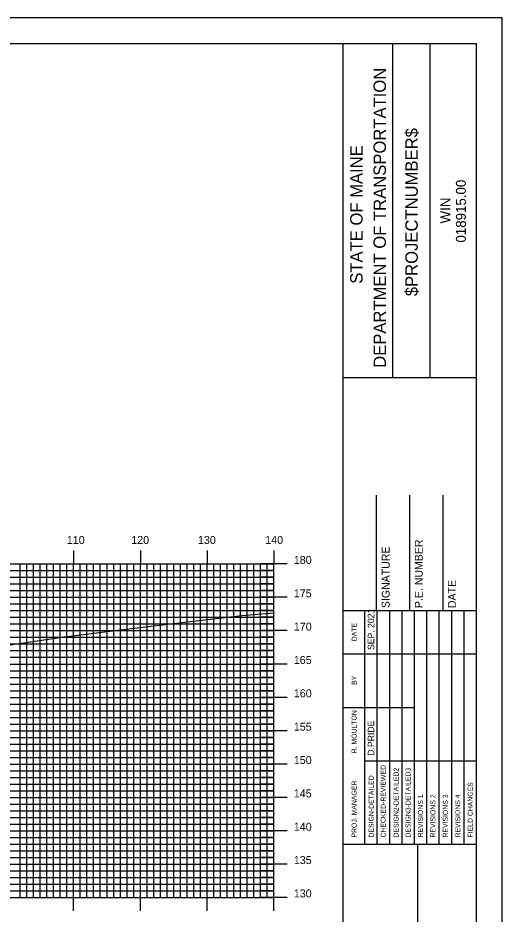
# Model space of a CAD drawing. Extents: x 1793272 to 1793615, y 442591 to 442811.
# Drawn here: x 1793539.4 to 1793612, y 442676.2 to 442810.5 of the extents above; entities that cross this region are included whole.
import ezdxf

# ---------------------------------------------------------------- set-up
doc = ezdxf.new("R2010")
doc.units = 0
for name, color, linetype in [('BORDER', 7, 'Continuous'), ('H_V ANNOTATION', 7, 'Continuous'), ('MAJOR', 7, 'Continuous'), ('MINOR', 7, 'Continuous'), ('PLOT BOUNDARY', 7, 'Continuous'), ('S_Roadway_Centerline', 7, 'Continuous')]:
    doc.layers.add(name, color=color, linetype=linetype)

msp = doc.modelspace()

# ---------------------------------------------------------------- linework, layer by layer
at = {"layer": 'BORDER'}
for p, q in [((1793588.2, 442596.67), (1793588.2, 442806.67)), ((1793595.66, 442756.66), (1793595.66, 442806.66)), ((1793601.25, 442756.66), (1793601.25, 442806.66)), ((1793588.2, 442756.65), (1793608.2, 442756.65)), ((1793593.2, 442721.67), (1793593.2, 442738.97)), ((1793598.2, 442721.67), (1793598.2, 442738.97)), ((1793603.2, 442721.67), (1793603.2, 442738.97)), ((1793588.2, 442721.67), (1793608.2, 442721.67)), ((1793588.2, 442686.67), (1793608.2, 442686.67)), ((1793599.38, 442616.67), (1793599.38, 442686.67))]:
    msp.add_line(p, q, dxfattribs=at)
msp.add_lwpolyline([(1793288.2, 442596.67), (1793608.2, 442596.67), (1793608.2, 442806.67), (1793288.2, 442806.67)], close=True, dxfattribs=at)
for points in [[(1793591.43, 442715.17), (1793591.43, 442721.67)], [(1793593.3, 442686.68), (1793593.3, 442721.67)], [(1793595.16, 442721.67), (1793595.16, 442686.68)], [(1793597.02, 442686.68), (1793597.02, 442721.67)], [(1793598.89, 442686.68), (1793598.89, 442721.67)], [(1793600.75, 442686.68), (1793600.75, 442721.67)], [(1793602.61, 442686.68), (1793602.61, 442721.67)], [(1793604.48, 442686.68), (1793604.48, 442721.67)], [(1793606.34, 442686.68), (1793606.34, 442721.67)], [(1793591.43, 442686.68), (1793591.43, 442720.26)], [(1793588.2, 442715.17), (1793608.2, 442715.17)], [(1793588.2, 442707.17), (1793591.43, 442707.17)], [(1793591.43, 442707.17), (1793598.88, 442707.17)], [(1793591.43, 442699.17), (1793608.2, 442699.17)]]:
    msp.add_lwpolyline(points, dxfattribs=at)
at = {"layer": 'MAJOR'}
for p, q in [((1793547.8, 442730.67), (1793547.8, 442728.67)), ((1793557.8, 442730.67), (1793557.8, 442728.67)), ((1793567.8, 442730.67), (1793567.8, 442728.67)), ((1793577.8, 442730.67), (1793577.8, 442728.67)), ((1793297.8, 442728.67), (1793577.8, 442728.67)), ((1793297.8, 442728.67), (1793577.8, 442728.67)), ((1793547.8, 442678.67), (1793547.8, 442728.67)), ((1793557.8, 442678.67), (1793557.8, 442728.67)), ((1793567.8, 442678.67), (1793567.8, 442728.67)), ((1793579.8, 442728.67), (1793575.8, 442728.67)), ((1793577.8, 442678.67), (1793577.8, 442728.67)), ((1793577.8, 442678.67), (1793577.8, 442728.67)), ((1793297.8, 442723.67), (1793577.8, 442723.67)), ((1793579.8, 442723.67), (1793575.8, 442723.67)), ((1793297.8, 442718.67), (1793577.8, 442718.67)), ((1793579.8, 442718.67), (1793575.8, 442718.67)), ((1793297.8, 442713.67), (1793577.8, 442713.67)), ((1793579.8, 442713.67), (1793575.8, 442713.67)), ((1793297.8, 442708.67), (1793577.8, 442708.67)), ((1793579.8, 442708.67), (1793575.8, 442708.67)), ((1793297.8, 442703.67), (1793577.8, 442703.67)), ((1793579.8, 442703.67), (1793575.8, 442703.67)), ((1793297.8, 442698.67), (1793577.8, 442698.67)), ((1793579.8, 442698.67), (1793575.8, 442698.67)), ((1793297.8, 442693.67), (1793577.8, 442693.67)), ((1793579.8, 442693.67), (1793575.8, 442693.67)), ((1793297.8, 442688.67), (1793577.8, 442688.67)), ((1793579.8, 442688.67), (1793575.8, 442688.67)), ((1793297.8, 442683.67), (1793577.8, 442683.67)), ((1793579.8, 442683.67), (1793575.8, 442683.67)), ((1793297.8, 442678.67), (1793577.8, 442678.67)), ((1793297.8, 442678.67), (1793577.8, 442678.67)), ((1793547.8, 442676.66), (1793547.8, 442678.67)), ((1793557.8, 442676.66), (1793557.8, 442678.67)), ((1793567.8, 442676.66), (1793567.8, 442678.67)), ((1793579.8, 442678.67), (1793575.8, 442678.67)), ((1793577.8, 442676.66), (1793577.8, 442678.67))]:
    msp.add_line(p, q, dxfattribs=at)
at = {"layer": 'MINOR'}
for p, q in [((1793539.8, 442678.67), (1793539.8, 442728.67)), ((1793540.8, 442678.67), (1793540.8, 442728.67)), ((1793541.8, 442678.67), (1793541.8, 442728.67)), ((1793542.8, 442678.67), (1793542.8, 442728.67)), ((1793543.8, 442678.67), (1793543.8, 442728.67)), ((1793544.8, 442678.67), (1793544.8, 442728.67)), ((1793545.8, 442678.67), (1793545.8, 442728.67)), ((1793546.8, 442678.67), (1793546.8, 442728.67)), ((1793548.8, 442678.67), (1793548.8, 442728.67)), ((1793549.8, 442678.67), (1793549.8, 442728.67)), ((1793550.8, 442678.67), (1793550.8, 442728.67)), ((1793551.8, 442678.67), (1793551.8, 442728.67)), ((1793552.8, 442678.67), (1793552.8, 442728.67)), ((1793553.8, 442678.67), (1793553.8, 442728.67)), ((1793554.8, 442678.67), (1793554.8, 442728.67)), ((1793555.8, 442678.67), (1793555.8, 442728.67)), ((1793556.8, 442678.67), (1793556.8, 442728.67)), ((1793558.8, 442678.67), (1793558.8, 442728.67)), ((1793559.8, 442678.67), (1793559.8, 442728.67)), ((1793560.8, 442678.67), (1793560.8, 442728.67)), ((1793561.8, 442678.67), (1793561.8, 442728.67)), ((1793562.8, 442678.67), (1793562.8, 442728.67)), ((1793563.8, 442678.67), (1793563.8, 442728.67)), ((1793564.8, 442678.67), (1793564.8, 442728.67)), ((1793565.8, 442678.67), (1793565.8, 442728.67)), ((1793566.8, 442678.67), (1793566.8, 442728.67)), ((1793568.8, 442678.67), (1793568.8, 442728.67)), ((1793569.8, 442678.67), (1793569.8, 442728.67)), ((1793570.8, 442678.67), (1793570.8, 442728.67)), ((1793571.8, 442678.67), (1793571.8, 442728.67)), ((1793572.8, 442678.67), (1793572.8, 442728.67)), ((1793573.8, 442678.67), (1793573.8, 442728.67)), ((1793574.8, 442678.67), (1793574.8, 442728.67)), ((1793575.8, 442678.67), (1793575.8, 442728.67)), ((1793576.8, 442678.67), (1793576.8, 442728.67)), ((1793297.8, 442727.67), (1793577.8, 442727.67)), ((1793577.8, 442727.67), (1793575.8, 442727.67)), ((1793297.8, 442726.67), (1793577.8, 442726.67)), ((1793577.8, 442726.67), (1793575.8, 442726.67)), ((1793297.8, 442725.67), (1793577.8, 442725.67)), ((1793297.8, 442724.67), (1793577.8, 442724.67)), ((1793577.8, 442725.67), (1793575.8, 442725.67)), ((1793577.8, 442724.67), (1793575.8, 442724.67)), ((1793297.8, 442722.67), (1793577.8, 442722.67)), ((1793577.8, 442722.67), (1793575.8, 442722.67)), ((1793297.8, 442721.67), (1793577.8, 442721.67)), ((1793297.8, 442720.67), (1793577.8, 442720.67)), ((1793577.8, 442721.67), (1793575.8, 442721.67)), ((1793577.8, 442720.67), (1793575.8, 442720.67)), ((1793297.8, 442719.67), (1793577.8, 442719.67)), ((1793577.8, 442719.67), (1793575.8, 442719.67)), ((1793297.8, 442717.67), (1793577.8, 442717.67)), ((1793297.8, 442716.67), (1793577.8, 442716.67)), ((1793577.8, 442717.67), (1793575.8, 442717.67)), ((1793577.8, 442716.67), (1793575.8, 442716.67)), ((1793297.8, 442715.67), (1793577.8, 442715.67)), ((1793577.8, 442715.67), (1793575.8, 442715.67)), ((1793297.8, 442714.67), (1793577.8, 442714.67)), ((1793577.8, 442714.67), (1793575.8, 442714.67)), ((1793297.8, 442712.67), (1793577.8, 442712.67)), ((1793577.8, 442712.67), (1793575.8, 442712.67)), ((1793297.8, 442711.67), (1793577.8, 442711.67)), ((1793577.8, 442711.67), (1793575.8, 442711.67)), ((1793297.8, 442710.67), (1793577.8, 442710.67)), ((1793577.8, 442710.67), (1793575.8, 442710.67)), ((1793297.8, 442709.67), (1793577.8, 442709.67)), ((1793577.8, 442709.67), (1793575.8, 442709.67)), ((1793297.8, 442707.67), (1793577.8, 442707.67)), ((1793577.8, 442707.67), (1793575.8, 442707.67)), ((1793297.8, 442706.67), (1793577.8, 442706.67)), ((1793577.8, 442706.67), (1793575.8, 442706.67)), ((1793297.8, 442705.67), (1793577.8, 442705.67)), ((1793297.8, 442704.67), (1793577.8, 442704.67)), ((1793577.8, 442705.67), (1793575.8, 442705.67)), ((1793577.8, 442704.67), (1793575.8, 442704.67)), ((1793297.8, 442702.67), (1793577.8, 442702.67)), ((1793577.8, 442702.67), (1793575.8, 442702.67)), ((1793297.8, 442701.67), (1793577.8, 442701.67)), ((1793297.8, 442700.67), (1793577.8, 442700.67)), ((1793577.8, 442701.67), (1793575.8, 442701.67)), ((1793577.8, 442700.67), (1793575.8, 442700.67)), ((1793297.8, 442699.67), (1793577.8, 442699.67)), ((1793577.8, 442699.67), (1793575.8, 442699.67)), ((1793297.8, 442697.67), (1793577.8, 442697.67)), ((1793297.8, 442696.67), (1793577.8, 442696.67)), ((1793577.8, 442697.67), (1793575.8, 442697.67)), ((1793577.8, 442696.67), (1793575.8, 442696.67)), ((1793297.8, 442695.67), (1793577.8, 442695.67)), ((1793577.8, 442695.67), (1793575.8, 442695.67)), ((1793297.8, 442694.67), (1793577.8, 442694.67)), ((1793577.8, 442694.67), (1793575.8, 442694.67)), ((1793297.8, 442692.67), (1793577.8, 442692.67)), ((1793577.8, 442692.67), (1793575.8, 442692.67)), ((1793297.8, 442691.67), (1793577.8, 442691.67)), ((1793577.8, 442691.67), (1793575.8, 442691.67)), ((1793297.8, 442690.67), (1793577.8, 442690.67)), ((1793297.8, 442689.67), (1793577.8, 442689.67)), ((1793577.8, 442690.67), (1793575.8, 442690.67)), ((1793577.8, 442689.67), (1793575.8, 442689.67)), ((1793297.8, 442687.67), (1793577.8, 442687.67)), ((1793577.8, 442687.67), (1793575.8, 442687.67)), ((1793297.8, 442686.67), (1793577.8, 442686.67)), ((1793297.8, 442685.67), (1793577.8, 442685.67)), ((1793577.8, 442686.67), (1793575.8, 442686.67)), ((1793577.8, 442685.67), (1793575.8, 442685.67)), ((1793297.8, 442684.67), (1793577.8, 442684.67)), ((1793577.8, 442684.67), (1793575.8, 442684.67)), ((1793297.8, 442682.67), (1793577.8, 442682.67)), ((1793297.8, 442681.67), (1793577.8, 442681.67)), ((1793577.8, 442682.67), (1793575.8, 442682.67)), ((1793577.8, 442681.67), (1793575.8, 442681.67)), ((1793297.8, 442680.67), (1793577.8, 442680.67)), ((1793577.8, 442680.67), (1793575.8, 442680.67)), ((1793297.8, 442679.67), (1793577.8, 442679.67)), ((1793577.8, 442679.67), (1793575.8, 442679.67))]:
    msp.add_line(p, q, dxfattribs=at)
at = {"layer": 'PLOT BOUNDARY'}
msp.add_lwpolyline([(1793272.01, 442590.55), (1793612.01, 442590.55), (1793612.01, 442810.55), (1793272.01, 442810.55)], close=True, dxfattribs=at)
at = {"layer": 'S_Roadway_Centerline'}
msp.add_lwpolyline([(1793535.23, 442716.08), (1793546.03, 442717.67), (1793554.01, 442718.69), (1793558.19, 442719.2), (1793564.89, 442719.99), (1793573.03, 442720.93), (1793577.8, 442721.33)], dxfattribs=at)

# ---------------------------------------------------------------- texts
at = {"layer": 'BORDER'}
for s, height, p in [('DEPARTMENT OF TRANSPORTATION', 1.8635, (1793594.61, 442758.08)), ('$PROJECTNUMBER$', 1.8635, (1793599.38, 442768.82)), ('STATE OF MAINE', 1.8635, (1793591.11, 442770.69)), ('018915.00', 1.491, (1793606.59, 442776.86)), ('WIN', 1.491, (1793604.27, 442779.73)), ('P.E. NUMBER', 1.1811, (1793600.12, 442722.06)), ('SIGNATURE', 1.181, (1793595.16, 442722.06)), ('DATE', 1.181, (1793605.08, 442722.06)), ('SEP. 2021', 0.969, (1793592.85, 442715.76)), ('DATE', 0.743, (1793590.21, 442717.08)), ('BY', 0.743, (1793590.21, 442710.54)), ('R. MOULTON', 0.745, (1793590.21, 442700.28)), ('D.PRIDE', 0.969, (1793592.85, 442699.92)), ('CHECKED-REVIEWED', 0.7455, (1793594.56, 442687.65)), ('DESIGN2-DETAILED2', 0.7455, (1793596.5, 442687.65)), ('DESIGN3-DETAILED3', 0.7455, (1793598.29, 442687.65)), ('DESIGN-DETAILED', 0.7455, (1793592.77, 442687.65)), ('PROJ. MANAGER', 0.7455, (1793590.21, 442687.65)), ('FIELD CHANGES', 0.7455, (1793607.61, 442687.65)), ('REVISIONS 1', 0.7455, (1793600.15, 442687.65)), ('REVISIONS 2', 0.7455, (1793602.02, 442687.65)), ('REVISIONS 3', 0.7455, (1793603.88, 442687.65)), ('REVISIONS 4', 0.7455, (1793605.74, 442687.65))]:
    msp.add_text(s, height=height, rotation=90, dxfattribs=at).set_placement(p)
at = {"layer": 'H_V ANNOTATION'}
for s, p in [('110', (1793546.78, 442731.67)), ('120', (1793556.44, 442731.67)), ('130', (1793566.43, 442731.67)), ('140', (1793576.51, 442731.67)), ('180', (1793580.8, 442728.67)), ('175', (1793580.8, 442723.67)), ('170', (1793580.8, 442718.67)), ('165', (1793580.8, 442713.67)), ('160', (1793580.8, 442708.67)), ('155', (1793580.8, 442703.67)), ('150', (1793580.8, 442698.67)), ('145', (1793580.8, 442693.67)), ('140', (1793580.8, 442688.67)), ('135', (1793580.8, 442683.67)), ('130', (1793580.8, 442678.67))]:
    msp.add_text(s, height=1.2, dxfattribs=at).set_placement(p)

doc.saveas('drawing.dxf')
